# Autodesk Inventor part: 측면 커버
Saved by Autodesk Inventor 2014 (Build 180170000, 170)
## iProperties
Created: 2026-05
Part Number: 측면 커버
Material: 알루미늄 6061
Document SubType Name: Modeling
Designer: dg
Density: 2.71 g/cm^3
Appearance: 알루미늄 - 평지
Mass: 335.737 g
Surface Area: 365.719 cm^2
Volume: 123.888 cm^3
Author: jhkim
Creation Date: 2026-04-23
Sending System: Autodesk Inventor 2027
Preprocessor: ST-DEVELOPER v20.1
Author: dg
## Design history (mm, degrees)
node "측면 커버1"
node "솔리드1"
node "기준1"
